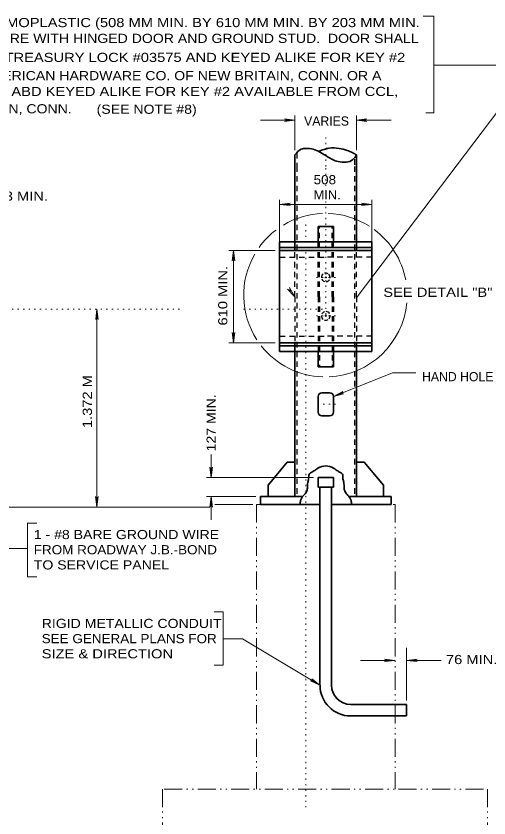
# Model space of a CAD drawing. Extents: x 312583 to 312854, y 144419 to 144597.
# Drawn here: x 312764.1 to 312803.4, y 144478.4 to 144545 of the extents above; entities that cross this region are included whole.
import ezdxf

# ---------------------------------------------------------------- set-up
doc = ezdxf.new("R2010")
doc.units = 0
doc.header["$LTSCALE"] = 0.3
for name, pattern in [('DASH_DOUBLE_DOT', [9.2, 5, -1.2, 0.3, -1.2, 0.3, -1.2]), ('DOTTED', [1.5, 0.3, -1.2]), ('LONG_DASH_SHORT_DASH', [9.9, 6, -1.2, 1.5, -1.2]), ('SHORT_DASHED', [2.7, 1.5, -1.2])]:
    doc.linetypes.add(name, pattern=pattern)
doc.layers.add('1', color=7, linetype='Continuous', lineweight=13)

msp = doc.modelspace()

# ---------------------------------------------------------------- linework, layer by layer
at = {"layer": '1'}
for p, q in [((312792.4809, 144521.6853), (312806.9054, 144540.7371)), ((312798.8325, 144540.9002), (312807.0289, 144540.9002)), ((312787.3027, 144533.8453), (312787.3027, 144536.7203)), ((312792.4164, 144533.8453), (312792.4164, 144536.7203)), ((312787.3027, 144536.337), (312784.4277, 144536.337)), ((312786.4364, 144536.4443), (312786.7124, 144536.337)), ((312787.3027, 144536.337), (312786.4364, 144536.4443)), ((312786.4364, 144536.2296), (312786.7124, 144536.337)), ((312787.3027, 144536.337), (312786.4364, 144536.2296)), ((312792.4164, 144536.337), (312793.2827, 144536.4443)), ((312792.4164, 144536.337), (312795.2914, 144536.337)), ((312792.4164, 144536.337), (312793.2827, 144536.2296)), ((312793.2827, 144536.4443), (312793.0067, 144536.337)), ((312793.2827, 144536.2296), (312793.0067, 144536.337)), ((312786.0301, 144525.902), (312786.0301, 144529.7353)), ((312786.0301, 144529.352), (312786.8964, 144529.4593)), ((312786.8964, 144529.4593), (312786.6204, 144529.352)), ((312792.8304, 144529.4593), (312793.1064, 144529.352)), ((312793.6967, 144529.352), (312792.8304, 144529.4593)), ((312793.6967, 144525.902), (312793.6967, 144529.7353)), ((312786.0301, 144529.352), (312793.6967, 144529.352)), ((312786.0301, 144529.352), (312786.8964, 144529.2447)), ((312786.8964, 144529.2447), (312786.6204, 144529.352)), ((312792.8304, 144529.2447), (312793.1064, 144529.352)), ((312793.6967, 144529.352), (312792.8304, 144529.2447)), ((312785.6467, 144525.5187), (312781.8134, 144525.5187)), ((312782.1967, 144525.5187), (312782.0894, 144524.6523)), ((312782.1967, 144517.852), (312782.1967, 144525.5187)), ((312782.1967, 144525.5187), (312782.3041, 144524.6523)), ((312782.0894, 144524.6523), (312782.1967, 144524.9283)), ((312782.3041, 144524.6523), (312782.1967, 144524.9283)), ((312789.8634, 144523.2877), (312789.7867, 144523.2877)), ((312789.8634, 144523.2877), (312789.8634, 144523.3643)), ((312789.8634, 144523.2877), (312789.9401, 144523.2877)), ((312789.8634, 144523.2877), (312789.8634, 144523.211)), ((312786.679, 144522.3044), (312786.9371, 144522.1549)), ((312787.3027, 144521.6853), (312786.679, 144522.3044)), ((312786.8496, 144522.4329), (312786.9371, 144522.1549)), ((312787.3027, 144521.6853), (312786.8496, 144522.4329)), ((312770.8565, 144520.6444), (312770.7492, 144519.7781)), ((312770.8424, 144504.213), (312770.8424, 144520.6544)), ((312770.8565, 144520.6444), (312770.9639, 144519.7781)), ((312789.8634, 144520.0907), (312789.7867, 144520.0907)), ((312789.8634, 144520.0907), (312789.8634, 144520.1673)), ((312789.8634, 144520.0907), (312789.9401, 144520.0907)), ((312789.8634, 144520.0907), (312789.8634, 144520.014)), ((312770.7492, 144519.7781), (312770.8565, 144520.0541)), ((312770.9639, 144519.7781), (312770.8565, 144520.0541)), ((312782.0894, 144518.7183), (312782.1967, 144518.4423)), ((312782.1967, 144517.852), (312782.0894, 144518.7183)), ((312782.3041, 144518.7183), (312782.1967, 144518.4423)), ((312782.1967, 144517.852), (312782.3041, 144518.7183)), ((312785.6467, 144517.852), (312781.8134, 144517.852)), ((312790.4997, 144513.3823), (312795.4141, 144515.3603)), ((312797.3307, 144515.3603), (312795.4141, 144515.3603)), ((312790.4997, 144513.3823), (312791.2664, 144513.804)), ((312790.4997, 144513.3823), (312791.3431, 144513.6047)), ((312791.2664, 144513.804), (312791.0517, 144513.6047)), ((312791.3431, 144513.6047), (312791.0517, 144513.6047)), ((312780.3414, 144506.674), (312780.3414, 144508.5907)), ((312780.2341, 144507.5403), (312780.3414, 144507.2643)), ((312780.3414, 144506.674), (312780.2341, 144507.5403)), ((312780.4487, 144507.5403), (312780.3414, 144507.2643)), ((312780.3414, 144506.674), (312780.4487, 144507.5403)), ((312788.8361, 144506.674), (312779.9581, 144506.674)), ((312770.7351, 144505.0794), (312770.8424, 144504.8034)), ((312770.8424, 144504.213), (312770.7351, 144505.0794)), ((312770.9498, 144505.0794), (312770.8424, 144504.8034)), ((312770.8424, 144504.213), (312770.9498, 144505.0794)), ((312784.0444, 144505.0793), (312779.9581, 144505.0793)), ((312780.3414, 144505.0793), (312780.2341, 144504.213)), ((312780.3414, 144505.0793), (312780.3414, 144503.1627)), ((312780.3414, 144505.0793), (312780.4487, 144504.213)), ((312780.2341, 144504.213), (312761.8494, 144504.213)), ((312780.2341, 144504.213), (312780.3414, 144504.489)), ((312780.4487, 144504.213), (312780.3414, 144504.489)), ((312783.7914, 144504.4353), (312780.6404, 144504.4353)), ((312765.0915, 144502.877), (312765.8582, 144502.877)), ((312765.0915, 144498.4303), (312765.8582, 144498.4303)), ((312781.3448, 144495.5238), (312780.5781, 144495.5238)), ((312782.9327, 144493.2803), (312781.3448, 144493.2803)), ((312789.3804, 144489.424), (312782.9327, 144493.2803)), ((312796.5717, 144488.1437), (312796.5717, 144492.5395)), ((312792.7384, 144491.4858), (312795.6134, 144491.4858)), ((312794.7471, 144491.5931), (312795.0231, 144491.4858)), ((312795.6134, 144491.4858), (312794.7471, 144491.5931)), ((312794.7471, 144491.3785), (312795.0231, 144491.4858)), ((312795.6134, 144491.4858), (312794.7471, 144491.3785)), ((312796.5717, 144491.4858), (312797.4381, 144491.5931)), ((312796.5717, 144491.4858), (312799.4467, 144491.4858)), ((312796.5717, 144491.4858), (312797.4381, 144491.3785)), ((312797.4381, 144491.5931), (312797.1621, 144491.4858)), ((312797.4381, 144491.3785), (312797.1621, 144491.4858)), ((312781.3448, 144491.0771), (312780.5781, 144491.0771)), ((312788.5831, 144489.7767), (312788.8744, 144489.7307)), ((312789.3804, 144489.424), (312788.5831, 144489.7767)), ((312788.6981, 144489.9607), (312788.8744, 144489.7307)), ((312789.3804, 144489.424), (312788.6981, 144489.9607))]:
    msp.add_line(p, q, dxfattribs=at)
at = {"layer": '1', "linetype": 'DOTTED'}
for p, q in [((312788.1919, 144527.6693), (312788.1919, 144479.2849)), ((312789.6411, 144523.2877), (312788.9894, 144523.2877)), ((312789.8634, 144520.2057), (312789.8634, 144523.05)), ((312790.1011, 144523.2877), (312790.7297, 144523.2877)), ((312777.7093, 144520.6544), (312752.7856, 144520.6544)), ((312789.5779, 144520.6544), (312782.7056, 144520.6544)), ((312789.6411, 144520.0907), (312788.9894, 144520.0907)), ((312790.1011, 144520.0907), (312790.7297, 144520.0907)), ((312790.6761, 144512.769), (312788.9894, 144512.769))]:
    msp.add_line(p, q, dxfattribs=at)
at = {"layer": '1', "lineweight": 35}
for p, q in [((312789.2194, 144527.5197), (312789.8634, 144527.5197)), ((312789.2194, 144526.2393), (312789.2194, 144527.5197)), ((312790.4997, 144527.5197), (312789.8634, 144527.5197)), ((312790.4997, 144526.2393), (312790.4997, 144527.5197)), ((312786.0301, 144526.2393), (312789.8634, 144526.2393)), ((312786.0301, 144521.6853), (312786.0301, 144526.2393)), ((312793.6967, 144526.2393), (312789.8634, 144526.2393)), ((312793.6967, 144521.6853), (312793.6967, 144526.2393)), ((312786.0301, 144525.764), (312789.8634, 144525.764)), ((312786.0301, 144525.5187), (312789.8634, 144525.5187)), ((312793.6967, 144525.764), (312789.8634, 144525.764)), ((312793.6967, 144525.5187), (312789.8634, 144525.5187)), ((312786.0301, 144521.6853), (312786.0301, 144517.139)), ((312793.6967, 144521.6853), (312793.6967, 144517.139)), ((312786.0301, 144517.852), (312789.8634, 144517.852)), ((312786.0301, 144517.6143), (312789.8634, 144517.6143)), ((312787.3027, 144517.852), (312787.3027, 144505.0793)), ((312793.6967, 144517.852), (312789.8634, 144517.852)), ((312793.6967, 144517.6143), (312789.8634, 144517.6143)), ((312792.4164, 144517.852), (312792.4164, 144505.0793)), ((312786.0301, 144517.139), (312789.8634, 144517.139)), ((312789.2194, 144517.139), (312789.2194, 144515.8587)), ((312793.6967, 144517.139), (312789.8634, 144517.139)), ((312790.4997, 144517.139), (312790.4997, 144515.8587)), ((312789.2194, 144515.8587), (312789.8634, 144515.8587)), ((312790.4997, 144515.8587), (312789.8634, 144515.8587)), ((312789.5414, 144513.7043), (312789.8634, 144513.7043)), ((312790.1777, 144513.7043), (312789.8634, 144513.7043)), ((312789.2194, 144513.3823), (312789.2194, 144512.102)), ((312790.4997, 144513.3823), (312790.4997, 144512.102)), ((312789.5414, 144511.7877), (312789.8634, 144511.7877)), ((312790.1777, 144511.7877), (312789.8634, 144511.7877)), ((312786.6664, 144507.9543), (312785.0717, 144506.0377)), ((312787.3027, 144507.9543), (312786.6664, 144507.9543)), ((312792.4164, 144507.9543), (312793.0527, 144507.9543)), ((312793.0527, 144507.9543), (312794.6551, 144506.0377)), ((312789.2194, 144506.674), (312789.8634, 144506.674)), ((312789.2194, 144505.8767), (312789.2194, 144506.674)), ((312790.4997, 144506.674), (312789.8634, 144506.674)), ((312785.0717, 144505.0793), (312785.0717, 144506.0377)), ((312789.2194, 144505.8767), (312789.8634, 144505.8767)), ((312789.3804, 144505.8767), (312789.3804, 144489.424)), ((312790.3387, 144505.8767), (312790.3387, 144489.424)), ((312794.6551, 144505.0793), (312794.6551, 144506.0377)), ((312784.4277, 144505.0793), (312787.9391, 144505.0793)), ((312784.4277, 144505.0793), (312784.4277, 144504.4353)), ((312795.2914, 144505.0793), (312791.7877, 144505.0793)), ((312795.2914, 144505.0793), (312795.2914, 144504.4353)), ((312784.4277, 144504.4353), (312789.3804, 144504.4353)), ((312795.2914, 144504.4353), (312790.3387, 144504.4353)), ((312791.9411, 144487.8293), (312796.5717, 144487.8293)), ((312796.5717, 144487.8293), (312796.5717, 144486.871)), ((312791.9411, 144486.871), (312796.5717, 144486.871))]:
    msp.add_line(p, q, dxfattribs=at)
at = {"layer": '1', "linetype": 'SHORT_DASHED', "lineweight": 25}
for p, q in [((312789.3421, 144521.6853), (312789.3421, 144527.5197)), ((312790.3847, 144521.6853), (312790.3847, 144527.5197)), ((312789.2194, 144521.6853), (312789.2194, 144526.2393)), ((312790.4997, 144521.6853), (312790.4997, 144526.2393)), ((312787.3027, 144521.6853), (312787.3027, 144525.5187)), ((312792.4164, 144521.6853), (312792.4164, 144525.5187)), ((312786.0301, 144524.959), (312789.8634, 144524.959)), ((312793.6967, 144524.959), (312789.8634, 144524.959)), ((312787.3027, 144521.6853), (312787.3027, 144517.852)), ((312789.2194, 144521.6853), (312789.2194, 144517.139)), ((312789.3421, 144521.6853), (312789.3421, 144515.8587)), ((312790.3847, 144521.6853), (312790.3847, 144515.8587)), ((312790.4997, 144521.6853), (312790.4997, 144517.139)), ((312792.4164, 144521.6853), (312792.4164, 144517.852)), ((312786.0301, 144518.4117), (312789.8634, 144518.4117)), ((312793.6967, 144518.4117), (312789.8634, 144518.4117))]:
    msp.add_line(p, q, dxfattribs=at)
at = {"layer": '1', "linetype": 'DASH_DOUBLE_DOT'}
for p, q in [((312784.1134, 144504.4353), (312784.1134, 144480.799)), ((312795.6134, 144504.4353), (312795.6134, 144480.799)), ((312776.4467, 144480.799), (312803.2801, 144480.799)), ((312803.2801, 144480.799), (312803.2801, 144473.1323))]:
    msp.add_line(p, q, dxfattribs=at)
at = {"layer": '1', "linetype": 'LONG_DASH_SHORT_DASH'}
for p, q in [((312784.1134, 144504.4353), (312789.3804, 144504.4353)), ((312790.3387, 144504.4353), (312795.6134, 144504.4353))]:
    msp.add_line(p, q, dxfattribs=at)
at = {"layer": '1'}
for points in [[(312798.1742, 144536.9611), (312798.8325, 144536.9611), (312798.8325, 144544.9877), (312797.9574, 144544.9877)], [(312763.4748, 144503.914), (312762.9381, 144500.786), (312765.0915, 144500.786)], [(312765.0915, 144502.877), (312765.0915, 144502.0336), (312765.0915, 144498.4303)], [(312781.3448, 144495.5238), (312781.3448, 144494.6804), (312781.3448, 144491.0771)]]:
    msp.add_lwpolyline(points, dxfattribs=at)
at = {"layer": '1', "linetype": 'DOTTED'}
msp.add_lwpolyline([(312789.8634, 144523.5177), (312789.8634, 144532.5064), (312789.8634, 144535.049)], dxfattribs=at)
at = {"layer": '1', "lineweight": 35}
for points in [[(312787.3027, 144525.5187), (312787.3027, 144532.5064), (312787.3027, 144533.462)], [(312792.4164, 144525.5187), (312792.4164, 144532.5064), (312792.4164, 144533.462)], [(312790.4997, 144506.674), (312790.4997, 144505.8767), (312789.8634, 144505.8767)]]:
    msp.add_lwpolyline(points, dxfattribs=at)
at = {"layer": '1', "linetype": 'SHORT_DASHED', "lineweight": 25}
for points in [[(312787.4637, 144533.6076), (312787.4637, 144532.5064), (312787.4637, 144505.0793)], [(312792.2554, 144533.094), (312792.2554, 144532.5064), (312792.2554, 144505.0793)]]:
    msp.add_lwpolyline(points, dxfattribs=at)
at = {"layer": '1', "linetype": 'DASH_DOUBLE_DOT'}
msp.add_lwpolyline([(312776.3024, 144480.799), (312776.3024, 144473.1323), (312803.1358, 144473.1323)], dxfattribs=at)
at = {"layer": '1'}
for start, end in [(92.05712, 120.90448), (57.37801, 88.13041), (127.1732, 144.27657), (10.85678, 53.29193), (149.82648, 213.12292), (272.54872, 354.72577), (218.33899, 268.14496)]:
    msp.add_arc((312789.8305, 144521.8096), 6.7886, start, end, dxfattribs=at)
at = {"layer": '1', "lineweight": 25}
for centre, start, end in [((312789.8618, 144523.2848), 129.64999, 186.58194), ((312789.8618, 144523.2848), 55.99862, 107.31165), ((312789.8618, 144523.2848), 349.47353, 45.30076), ((312789.8618, 144523.2848), 201.54224, 252.23947), ((312789.8618, 144523.2848), 276.97206, 332.14555), ((312789.8618, 144520.0903), 173.41806, 230.35001), ((312789.8618, 144520.0903), 107.76053, 158.45776), ((312789.8618, 144520.0903), 27.85445, 83.02794), ((312789.8618, 144520.0903), 314.69924, 10.52647), ((312789.8618, 144520.0903), 252.68835, 304.00138)]:
    msp.add_arc(centre, 0.3594, start, end, dxfattribs=at)
at = {"layer": '1', "lineweight": 35}
for centre, radius, start, end in [((312789.5424, 144513.382), 0.3194, 90, 180), ((312790.1812, 144513.382), 0.3194, 0, 90), ((312789.5424, 144512.1042), 0.3194, 180, 270), ((312790.1812, 144512.1042), 0.3194, 270, 0), ((312791.9382, 144489.4237), 2.5556, 180, 270), ((312791.9382, 144489.4237), 1.5972, 180, 270)]:
    msp.add_arc(centre, radius, start, end, dxfattribs=at)
for points in [[(312792.4164, 144533.462), (312792.1097, 144533.623), (312791.6267, 144533.83), (312790.9597, 144533.9986), (312790.1394, 144534.0216), (312789.7177, 144533.9143), (312789.2731, 144533.7686)], [(312787.3027, 144533.462), (312787.8241, 144533.9373), (312788.2227, 144533.9986), (312788.8131, 144533.9373), (312789.3804, 144533.6843), (312790.0091, 144533.301), (312790.8907, 144532.9023), (312792.1097, 144533.071), (312792.4164, 144533.462)], [(312787.7167, 144504.4353), (312787.7704, 144504.765), (312788.0157, 144505.179), (312788.2534, 144505.478), (312788.3377, 144505.7923), (312788.3684, 144506.26), (312788.4374, 144506.559), (312788.4834, 144506.9423), (312788.7134, 144507.1263), (312789.0124, 144507.3027), (312789.2117, 144507.456), (312789.8634, 144507.6323)], [(312792.0024, 144504.4353), (312791.9564, 144504.765), (312791.7034, 144505.179), (312791.4734, 144505.478), (312791.3891, 144505.7923), (312791.3584, 144506.26), (312791.2894, 144506.559), (312791.2434, 144506.9423), (312791.0057, 144507.1263), (312790.7067, 144507.3027), (312790.5074, 144507.456), (312789.8634, 144507.6323)]]:
    msp.add_spline(points, degree=3, dxfattribs=at)

# ---------------------------------------------------------------- texts
at = {"layer": '1'}
for s, width, p in [('STRUCTURAL FOAM MOLDED THERMOPLASTIC (508 MM MIN. BY 610 MM MIN. BY 203 MM MIN.', 1.2, (312742.0362, 144544.0671)), ('-6 MM THK.UL LISTED ENCLOSURE WITH HINGED DOOR AND GROUND STUD.  DOOR SHALL', 1.15, (312745.4307, 144542.7542)), ('BE SECURED WITH A SUB-TREASURY LOCK #03575 AND KEYED ALIKE FOR KEY #2', 1.2, (312747.3921, 144541.1729)), ('AVAILABLE FROM THE AMERICAN HARDWARE CO. OF NEW BRITAIN, CONN. OR A', 1.15, (312748.1825, 144539.6587)), ('TUMBLER LOCK #1548IRS ABD KEYED ALIKE FOR KEY #2 AVAILABLE FROM CCL,', 1.2, (312748.1597, 144538.3458)), ('NEW BRITAIN, CONN.', 1.15, (312756.6842, 144536.9064)), ('(SEE NOTE #8)', 1.15, (312770.8289, 144536.8685)), ('508', 1.1, (312788.8506, 144531.0184)), ('203 MIN.', 1.2, (312761.8409, 144529.6536)), ('MIN.', 1.05, (312788.8506, 144529.7584)), ('SEE DETAIL "B"', 1.2, (312794.6418, 144521.671)), ('1 - #8 BARE GROUND WIRE', 1.15, (312765.6082, 144501.5539)), ('FROM ROADWAY J.B.-BOND', 1.1, (312765.6082, 144500.2939)), ('TO SERVICE PANEL', 1.15, (312765.6082, 144499.0339)), ('RIGID METALLIC CONDUIT', 1.15, (312766.2668, 144494.1725)), ('SEE GENERAL PLANS FOR', 1.1, (312766.2668, 144492.9125)), ('SIZE & DIRECTION', 1.2, (312766.2668, 144491.6525)), ('76 MIN.', 1.2, (312799.8425, 144491.1768))]:
    msp.add_text(s, height=0.76, dxfattribs=dict(at, width=width)).set_placement(p)
for s, p in [('VARIES', (312788.0602, 144535.8923)), ('HAND HOLE', (312797.856, 144514.6641))]:
    msp.add_text(s, height=0.76, dxfattribs=at).set_placement(p)
for s, width, p in [('610 MIN.', 1.2, (312781.6859, 144519.2898)), ('1.372 M', 1.2, (312770.4334, 144510.7682)), ('127 MIN.', 1.15, (312780.7206, 144508.8392))]:
    msp.add_text(s, height=0.76, rotation=90, dxfattribs=dict(at, width=width)).set_placement(p)

doc.saveas('drawing.dxf')
